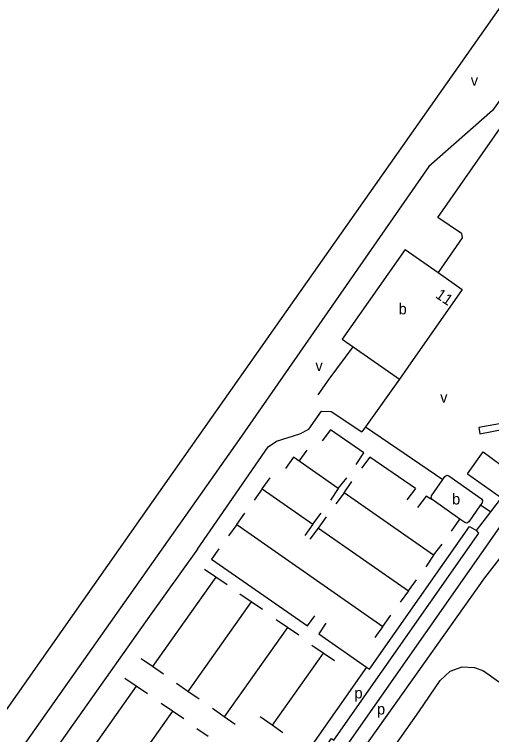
# Model space of a CAD drawing. Extents: x 154765 to 156627, y 383996 to 386132.
# Drawn here: x 155041.5 to 155215.9, y 385151.6 to 385414.8 of the extents above; entities that cross this region are included whole.
import ezdxf

# ---------------------------------------------------------------- set-up
doc = ezdxf.new("R2010")
doc.units = 0
for name, color, linetype in [('BLT_Basislijn', 7, 'Continuous'), ('BLT_Bebouwing', 7, 'Continuous'), ('BLT_Centroide', 7, 'Continuous'), ('BLT_Huisnummer', 7, 'Continuous')]:
    doc.layers.add(name, color=color, linetype=linetype)

msp = doc.modelspace()

# ---------------------------------------------------------------- linework, layer by layer
at = {"layer": 'BLT_Basislijn'}
for p, q in [((155156.57, 385281.47), (155165.22, 385293.39)), ((155152.51, 385275.82), (155156.57, 385281.47)), ((155182.19, 385281.51), (155169.75, 385264.14)), ((155169.75, 385264.14), (155168.42, 385262.28)), ((155169.75, 385264.14), (155198.08, 385244.87)), ((155145.49, 385251.5), (155148.47, 385255.6)), ((155166.37, 385250.3), (155169.19, 385254.59)), ((155207.11, 385246.88), (155212.78, 385254.9)), ((155212.78, 385254.9), (155224.59, 385246.22)), ((155171.4, 385253.06), (155168.35, 385248.93)), ((155188.08, 385241.5), (155171.4, 385253.06)), ((155207.11, 385246.88), (155219.47, 385238.15)), ((155132.01, 385241.42), (155134.99, 385245.44)), ((155159.76, 385241.57), (155162.93, 385245.51)), ((155161.98, 385240.02), (155164.84, 385244.15)), ((155132.01, 385241.42), (155129.13, 385237.28)), ((155132.01, 385241.42), (155150.5, 385228.55)), ((155159.76, 385241.57), (155157, 385237.34)), ((155188.08, 385241.5), (155184.83, 385237.47)), ((155161.98, 385240.02), (155158.96, 385235.97)), ((155194.64, 385217.18), (155161.98, 385240.02)), ((155192.01, 385238.78), (155188.81, 385234.66)), ((155215.54, 385233), (155219.47, 385238.15)), ((155211.81, 385235.54), (155215.54, 385233)), ((155122.75, 385228.45), (155125.65, 385232.5)), ((155150.5, 385228.55), (155153.54, 385232.53)), ((155223.98, 385234.96), (155153.88, 385134.89)), ((155210.33, 385226.16), (155215.54, 385233)), ((155152.57, 385227.11), (155155.5, 385231.16)), ((155201.23, 385226), (155204.28, 385230.4)), ((155122.75, 385228.45), (155119.76, 385224.31)), ((155122.75, 385228.45), (155176.14, 385191.14)), ((155150.5, 385228.55), (155147.64, 385224.38)), ((155149.57, 385222.99), (155152.57, 385227.11)), ((155152.57, 385227.11), (155185.53, 385204.18)), ((155228.9, 385229.37), (155213.32, 385208.88)), ((155116.25, 385219.51), (155113.58, 385215.78)), ((155194.64, 385217.18), (155197.76, 385221.2)), ((155194.64, 385217.18), (155191.88, 385212.99)), ((155113.58, 385215.78), (155148.54, 385191.39)), ((155115.11, 385209.18), (155110.97, 385211.98)), ((155115.11, 385209.18), (155091.93, 385176.45)), ((155119.25, 385206.37), (155115.11, 385209.18)), ((155185.53, 385204.18), (155188.38, 385208.21)), ((155185.53, 385204.18), (155182.49, 385200.04)), ((155128.05, 385200.11), (155123.91, 385202.91)), ((155128.05, 385200.11), (155104.86, 385167.36)), ((155132.19, 385197.31), (155128.05, 385200.11)), ((155141.26, 385190.71), (155137.12, 385193.51)), ((155148.54, 385191.39), (155151.31, 385195.02)), ((155176.14, 385191.14), (155179.02, 385195.22)), ((155141.26, 385190.71), (155118.17, 385158.1)), ((155145.4, 385187.9), (155141.26, 385190.71)), ((155155.3, 385192.33), (155152.69, 385188.49)), ((155176.04, 385191.05), (155173.18, 385187.05)), ((155152.69, 385188.49), (155170.21, 385176.26)), ((155154.37, 385181.4), (155150.23, 385184.2)), ((155154.37, 385181.4), (155135.74, 385155.09)), ((155158.51, 385178.59), (155154.37, 385181.4)), ((155091.93, 385176.45), (155087.79, 385179.25)), ((155095.95, 385173.73), (155091.93, 385176.45)), ((155170.21, 385176.26), (155145.22, 385140.85)), ((155086.01, 385169.34), (155081.87, 385172.14)), ((155086.01, 385169.34), (155057.14, 385128.56)), ((155090.16, 385166.54), (155086.01, 385169.34)), ((155104.86, 385167.36), (155100.76, 385170.34)), ((155109.03, 385164.53), (155104.86, 385167.36)), ((155099.3, 385160.16), (155095.16, 385162.96)), ((155099.3, 385160.16), (155070.32, 385119.22)), ((155103.44, 385157.35), (155099.3, 385160.16)), ((155118.17, 385158.1), (155113.88, 385161.15)), ((155122.17, 385155.36), (155118.17, 385158.1)), ((155135.74, 385155.09), (155131.35, 385158.05)), ((155112.33, 385150.97), (155108.19, 385153.78)), ((155139.61, 385152.26), (155135.74, 385155.09))]:
    msp.add_line(p, q, dxfattribs=at)
for points in [[(155001.53, 385107.93), (155095.72, 385242.01), (155221.63, 385421.26), (155278.06, 385501.59), (155307.92, 385531.59), (155362.73, 385609.97), (155374.64, 385636.58)], [(155234.74, 385412.07), (155228.58, 385403.41), (155224.55, 385391.47), (155216.21, 385379.72), (155192.97, 385359.25), (155123.67, 385259.51), (155043.61, 385145.9), (155014.37, 385104.41), (155012.61, 385102.8), (155010.41, 385101.87), (155008.28, 385101.81), (155005.41, 385102.5), (155003.02, 385104.02), (155002.04, 385105.22), (155001.66, 385106.08), (155001.51, 385106.85), (155001.53, 385107.93)], [(155204.86, 385334.76), (155196.2, 385340.65), (155225.22, 385382.15), (155227.66, 385382.48), (155251.67, 385365.82)], [(155204.86, 385334.76), (155205.1, 385333.16), (155196.28, 385320.5)], [(155108.39, 385219.41), (155134.17, 385256.84), (155137.28, 385258.82), (155145.84, 385261.48), (155149.04, 385263.27), (155153.69, 385269.83), (155157.28, 385269.75), (155168.42, 385262.28)], [(155220.06, 385265.38), (155211.16, 385263.89), (155211.57, 385261.6), (155220.38, 385263.19)], [(155169.19, 385254.59), (155156.96, 385263.06), (155153.97, 385258.96)], [(155159.76, 385241.57), (155143.49, 385252.96), (155140.52, 385248.84)], [(155194.17, 385237.49), (155193.23, 385237.93), (155192.01, 385238.78)], [(155170.21, 385176.26), (155171.2, 385175.57), (155207.82, 385227.66), (155210.33, 385226.16)], [(155145.22, 385140.85), (155148.83, 385138.37), (155157.37, 385150.17), (155158.23, 385149.59), (155211.18, 385225.29), (155210.33, 385226.16)], [(155108.39, 385219.41), (155090.89, 385194.93), (155003.26, 385071.14)], [(155213.32, 385208.88), (155183.52, 385166.98)], [(155147, 385099.88), (155189.27, 385159.89), (155197.12, 385171.44), (155200.67, 385174.74), (155205.13, 385176.33), (155209.65, 385176.09), (155212.87, 385174.9), (155288.69, 385121.24)], [(155183.52, 385166.98), (155164.42, 385140.11), (155162.53, 385137.4)]]:
    msp.add_lwpolyline(points, dxfattribs=at)
at = {"layer": 'BLT_Bebouwing'}
for p, q in [((155184.25, 385328.93), (155161.29, 385296.15)), ((155184.25, 385328.93), (155196.28, 385320.5)), ((155196.28, 385320.5), (155205.15, 385314.29)), ((155205.15, 385314.29), (155185.26, 385285.89)), ((155161.29, 385296.15), (155165.22, 385293.39)), ((155165.22, 385293.39), (155182.19, 385281.51)), ((155185.26, 385285.89), (155182.19, 385281.51)), ((155204.28, 385230.4), (155194.17, 385237.49))]:
    msp.add_line(p, q, dxfattribs=at)
for points in [[(155198.08, 385244.87), (155198.81, 385245.91), (155199.47, 385246.38), (155200.25, 385246.16), (155212.14, 385237.81), (155212.58, 385237.14), (155212.39, 385236.36), (155211.81, 385235.54)], [(155194.17, 385237.49), (155193.72, 385238.16), (155193.93, 385238.94), (155198.08, 385244.87)], [(155211.81, 385235.54), (155207.51, 385229.4), (155206.84, 385228.93), (155206.05, 385229.16), (155204.28, 385230.4)]]:
    msp.add_lwpolyline(points, dxfattribs=at)

# ---------------------------------------------------------------- texts
at = {"layer": 'BLT_Centroide'}
for s, p in [('v', (155208.24, 385388.74)), ('b', (155181.89, 385305.22)), ('v', (155151.49, 385284.5)), ('v', (155197.08, 385272.95)), ('b', (155201.41, 385235.72)), ('p', (155165.75, 385164.84)), ('p', (155173.99, 385158.96))]:
    msp.add_text(s, height=4, dxfattribs=at).set_placement(p)
at = {"layer": 'BLT_Huisnummer'}
msp.add_text('11', height=4, rotation=325.4768, dxfattribs=at).set_placement((155195.05, 385311.55))

doc.saveas('drawing.dxf')
